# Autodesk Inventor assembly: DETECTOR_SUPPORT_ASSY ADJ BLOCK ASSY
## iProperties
Shininess: 64.0
Length Units: 11272
Angle Units: 11279
Time Units: 11290
Mass Units: 11286
Length Display Precision: 3
Angle Display Precision: 2
Compacted: True
Part Number: DETECTOR_SUPPORT_ASSY ADJ BLOCK ASSY
Document SubType Name: Assembly
Created: 2004-08
Designer: John Blackburn
Manufacturer: Standard
Standards Organization: Custom
Density: 0.0
Volumn: 0.0
Area: 0.0
PropertySet Name: Model Information
Control State: 0
Master: False
Checked Out: False
Author: John Blackburn
